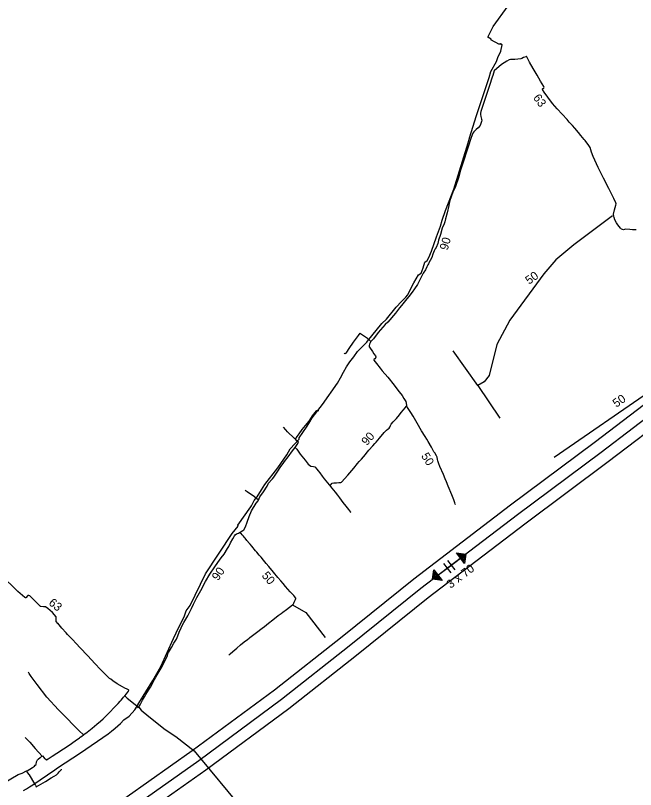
# Model space of a CAD drawing. Extents: x -444841 to -429545, y -1135312 to -1129851.
# Drawn here: x -442616 to -442033, y -1130962 to -1130233 of the extents above; entities that cross this region are included whole.
import ezdxf

# ---------------------------------------------------------------- set-up
doc = ezdxf.new("R2010")
doc.units = 0
for name, color, linetype in [('Vrstva 10', 7, 'Continuous'), ('Vrstva 13', 7, 'Continuous'), ('Vrstva 15', 7, 'Continuous'), ('Vrstva 27', 7, 'Continuous'), ('Vrstva 30', 7, 'Continuous'), ('Vrstva 35', 7, 'Continuous'), ('Vrstva 38', 7, 'Continuous'), ('Vrstva 58', 7, 'Continuous')]:
    doc.layers.add(name, color=color, linetype=linetype)

msp = doc.modelspace()

# ---------------------------------------------------------------- linework, layer by layer
at = {"layer": 'Vrstva 10'}
for p, q in [((-442209.39, -1130746.25), (-442206, -1130750.71)), ((-442213.18, -1130749.13), (-442209.79, -1130753.59)), ((-442209.79, -1130753.59), (-442206.4, -1130758.05)), ((-442206, -1130750.71), (-442202.61, -1130755.16))]:
    msp.add_line(p, q, dxfattribs=at)
for points in [[(-442545.2, -1131006.71), (-442443.5, -1130934.6), (-442365.65, -1130877.08), (-442301.93, -1130826.75), (-442234.54, -1130772.43), (-442143.45, -1130703.1), (-442064.73, -1130644.42), (-442003.9, -1130597.89), (-441963.63, -1130563.69)], [(-442218.48, -1130760.2), (-442207.89, -1130752.15), (-442197.31, -1130744.09)]]:
    msp.add_lwpolyline(points, dxfattribs=at)
for points in [[(-442201.13, -1130739.08), (-442192.3, -1130740.28), (-442193.49, -1130749.11)], [(-442199.54, -1130740), (-442193.09, -1130740.88), (-442193.96, -1130747.34)], [(-442197.97, -1130740.92), (-442193.87, -1130741.48), (-442194.43, -1130745.57)], [(-442196.38, -1130741.84), (-442194.66, -1130742.08), (-442194.89, -1130743.8)], [(-442222.29, -1130755.19), (-442214.66, -1130765.22), (-442223.49, -1130764.02)], [(-442221.83, -1130756.96), (-442216.24, -1130764.3), (-442222.7, -1130763.42)], [(-442221.36, -1130758.73), (-442217.82, -1130763.38), (-442221.92, -1130762.82)], [(-442220.89, -1130760.5), (-442219.4, -1130762.45), (-442221.13, -1130762.22)]]:
    msp.add_lwpolyline(points, close=True, dxfattribs=at)
at = {"layer": 'Vrstva 15'}
for points in [[(-441968.62, -1130553.5), (-442010.81, -1130589.32), (-442071.36, -1130635.64), (-442150.07, -1130694.32), (-442241.33, -1130763.77), (-442308.79, -1130818.15), (-442372.32, -1130868.34), (-442449.95, -1130925.69), (-442551.7, -1130997.84)], [(-442511.53, -1130996.32), (-442437.05, -1130943.51), (-442358.97, -1130885.82), (-442295.07, -1130835.35), (-442227.76, -1130781.09), (-442136.83, -1130711.89), (-442058.1, -1130653.2), (-441997, -1130606.45), (-441954.08, -1130570.1)]]:
    msp.add_lwpolyline(points, dxfattribs=at)
at = {"layer": 'Vrstva 27'}
for points in [[(-442079.9, -1130350.8), (-442080.72, -1130349.82), (-442083.95, -1130345.93), (-442086.15, -1130343.29), (-442089.78, -1130339.15), (-442091.92, -1130336.64), (-442094.89, -1130333.36), (-442096.98, -1130330.89), (-442101.71, -1130325.85), (-442106.2, -1130320.87), (-442110.6, -1130315.89), (-442115.09, -1130309.99), (-442118.55, -1130305.24), (-442120.18, -1130302.7), (-442120.27, -1130302.2), (-442120.02, -1130301.92), (-442118.78, -1130300.96), (-442118.58, -1130300.51), (-442118.71, -1130299.84), (-442121.95, -1130294.69), (-442125.17, -1130289.28), (-442128.95, -1130282.75), (-442132.23, -1130276.81), (-442134.8, -1130272.02), (-442135.03, -1130271.7), (-442135.38, -1130271.66), (-442135.88, -1130271.82), (-442137.84, -1130272.55), (-442139.54, -1130273.39), (-442140.42, -1130273.63), (-442146.25, -1130274.26), (-442150.32, -1130274.44), (-442151.4, -1130274.61), (-442153.72, -1130275.93), (-442158.67, -1130279.06), (-442165.58, -1130285.16)], [(-442165.58, -1130285.16), (-442166.88, -1130289.45), (-442167.31, -1130290.89), (-442170.05, -1130299.02), (-442171.29, -1130302.68), (-442174.92, -1130314.01), (-442178.05, -1130323.3), (-442178.43, -1130324.8), (-442178.55, -1130326.11), (-442178.07, -1130328.19), (-442177.45, -1130330.69), (-442177.24, -1130331.45), (-442177.48, -1130332.9), (-442178.76, -1130336.47), (-442180.61, -1130338.69), (-442182.41, -1130340.24), (-442184.85, -1130342.63), (-442185.71, -1130343.7), (-442186.41, -1130345.27), (-442187.82, -1130349.86), (-442189.76, -1130355.67), (-442191.72, -1130361.5), (-442193.78, -1130368.29), (-442197.14, -1130378.53)], [(-442031.87, -1130434.82), (-442035.46, -1130434.73), (-442037.75, -1130434.6), (-442042.06, -1130434.37), (-442043.97, -1130434.71), (-442045.64, -1130434.34), (-442046.75, -1130433.21), (-442049.07, -1130430.15), (-442050.26, -1130428.27), (-442051.88, -1130425.52), (-442052.67, -1130423.1), (-442052.98, -1130422.13), (-442053.1, -1130419.95), (-442052.32, -1130416.01), (-442050.91, -1130411.56), (-442050.78, -1130410.39), (-442050.99, -1130409.38), (-442052.9, -1130405.32), (-442057.74, -1130395.86), (-442062.69, -1130386.17), (-442067.8, -1130376.28), (-442072.48, -1130365.85), (-442073.91, -1130361.78), (-442075.3, -1130357.4), (-442076.35, -1130355.52), (-442079.9, -1130350.8)], [(-442197.14, -1130378.53), (-442199.28, -1130385.84), (-442201.84, -1130393.88), (-442204.37, -1130399.52), (-442207.36, -1130407.29), (-442208.2, -1130411.49), (-442208.3, -1130411.94), (-442209.73, -1130418.71), (-442211.51, -1130424.6), (-442212.15, -1130427.18), (-442212.65, -1130429.19), (-442214.45, -1130433.28), (-442216.13, -1130439.14), (-442217.86, -1130444.64), (-442218.73, -1130447.74), (-442220.3, -1130451.38), (-442221.02, -1130452.76), (-442222.1, -1130454.69), (-442223.41, -1130457.92), (-442224.26, -1130460.77), (-442225.8, -1130463.81), (-442227.12, -1130465.98), (-442227.4, -1130466.84), (-442227.85, -1130467.76), (-442228.85, -1130469.66), (-442230.13, -1130472.5), (-442232.42, -1130475.81), (-442235.19, -1130481.27), (-442237.14, -1130485.18), (-442237.76, -1130486.34), (-442240.52, -1130490.32), (-442242.89, -1130493.56), (-442245.96, -1130497.55), (-442247.87, -1130500)], [(-442247.87, -1130500), (-442250.29, -1130503.1), (-442252.71, -1130506.19), (-442254.54, -1130508.41), (-442258.54, -1130513.22), (-442265.66, -1130521.68), (-442268.09, -1130524.15), (-442274.83, -1130531.51), (-442279.22, -1130537.52), (-442281.59, -1130540.08)], [(-442291.86, -1130532.26), (-442293.5, -1130534.34), (-442298.37, -1130540.81), (-442302.22, -1130546.52), (-442304.59, -1130550.11), (-442305.44, -1130551.26), (-442306.03, -1130551.54), (-442306.68, -1130551.07)], [(-442281.59, -1130540.08), (-442284.89, -1130537.26), (-442291.32, -1130532.73), (-442291.86, -1130532.26)], [(-442281.59, -1130540.08), (-442281.92, -1130540.44), (-442282.37, -1130541.45), (-442282.77, -1130542.51), (-442283.29, -1130543.91), (-442283.21, -1130545.01), (-442282.95, -1130545.37), (-442280.01, -1130549.48), (-442278.78, -1130551.68), (-442277.22, -1130553.46), (-442276.85, -1130554.39), (-442276.61, -1130554.7), (-442276.87, -1130555.21), (-442277.89, -1130556.25), (-442278.86, -1130557.03), (-442278.95, -1130557.34), (-442278.8, -1130557.7), (-442276.4, -1130560.61), (-442272.79, -1130565.13), (-442270.84, -1130567.52), (-442265.7, -1130573.69), (-442259.83, -1130581.08), (-442257.28, -1130584.49), (-442254.94, -1130587.37), (-442252.29, -1130591.04), (-442250.71, -1130593.82), (-442248.82, -1130596.69), (-442248.31, -1130598.28), (-442248.06, -1130600.2), (-442248.38, -1130601.16)], [(-442320.61, -1130675.22), (-442319.77, -1130675.24), (-442318, -1130673.6), (-442316.5, -1130673.1), (-442314.08, -1130673.02), (-442311.65, -1130672.81), (-442309.84, -1130672.87), (-442309.29, -1130672.67), (-442303.37, -1130665.98), (-442297.79, -1130659.41), (-442294.18, -1130655.11), (-442292.52, -1130653.2), (-442290.57, -1130651.03), (-442286.77, -1130646.54), (-442285.98, -1130645.6), (-442283.39, -1130642.49), (-442279.7, -1130638.26), (-442277.87, -1130636.14), (-442276.71, -1130634.79), (-442273.61, -1130631.14), (-442269.14, -1130625.83), (-442266.9, -1130623.42), (-442265.42, -1130622.43), (-442264.32, -1130621.65), (-442263.64, -1130620.72), (-442263.12, -1130619.28), (-442262.65, -1130617.96), (-442260.54, -1130615.63), (-442257.6, -1130612.52), (-442254.77, -1130609.08), (-442253.03, -1130606.84), (-442251.01, -1130604.47), (-442249.25, -1130602.43), (-442248.38, -1130601.16)], [(-442201.94, -1130693.46), (-442202.21, -1130693.17), (-442202.65, -1130691.93), (-442203.45, -1130689.31), (-442205.53, -1130684.39), (-442208.76, -1130676.37), (-442210.5, -1130672.15), (-442211.65, -1130669.38), (-442213.38, -1130665.19), (-442216.65, -1130657.73), (-442217.63, -1130655.34), (-442218.73, -1130652.39), (-442218.94, -1130651.34), (-442219.32, -1130649.02), (-442219.85, -1130647.62), (-442221.48, -1130644.78), (-442222.29, -1130643.91), (-442222.7, -1130643.48), (-442224.43, -1130639.7), (-442227.65, -1130634.29), (-442228.93, -1130632.16), (-442230.36, -1130629.68), (-442233.87, -1130624.07), (-442238.08, -1130616.86), (-442241.92, -1130610.41), (-442244.07, -1130606.83), (-442247.26, -1130602.3), (-442248.38, -1130601.16)], [(-442352.69, -1130632.19), (-442350.93, -1130629.68), (-442349.03, -1130627.11), (-442346.18, -1130623.08), (-442343.03, -1130619.16), (-442339.76, -1130615.19), (-442336.51, -1130610), (-442332.91, -1130605.29), (-442332.52, -1130605.05), (-442331.52, -1130604.93), (-442330.64, -1130604.95)], [(-442353.75, -1130631.17), (-442360.16, -1130624.99), (-442361.82, -1130623.33), (-442363.89, -1130620.79)], [(-442352.69, -1130632.19), (-442353.49, -1130631.42), (-442353.75, -1130631.17)], [(-442352.75, -1130640.01), (-442352.32, -1130638.86), (-442351.13, -1130637.01), (-442349.75, -1130635.02), (-442351.18, -1130633.69), (-442352.69, -1130632.19)], [(-442387.32, -1130689.35), (-442386.01, -1130686.48), (-442382.71, -1130681.51), (-442379.25, -1130676.28), (-442378.01, -1130673.54), (-442374.87, -1130670.06), (-442374.38, -1130669.55), (-442373.1, -1130667.99), (-442369.84, -1130663.28), (-442366.23, -1130657.88), (-442364.28, -1130654.99), (-442362.81, -1130653.05), (-442359.56, -1130648.67), (-442355.25, -1130642.91), (-442352.75, -1130640.01)], [(-442352.75, -1130640.01), (-442351.33, -1130641.47), (-442348.04, -1130646.25), (-442343.34, -1130651.95), (-442340.59, -1130655.7), (-442338.07, -1130657.38), (-442335.73, -1130657.72), (-442334.28, -1130658.1), (-442334.08, -1130658.35), (-442332.49, -1130660.29), (-442331.1, -1130661.99), (-442329.7, -1130663.86), (-442327.39, -1130666.83), (-442325.44, -1130669.32), (-442322.51, -1130673.1), (-442320.92, -1130675), (-442320.61, -1130675.22)], [(-442320.61, -1130675.22), (-442318.48, -1130678.11), (-442315.37, -1130681.85), (-442313, -1130684.89), (-442311.23, -1130687.28), (-442307.97, -1130691.59), (-442305.32, -1130695.09), (-442302.73, -1130698.36), (-442300.88, -1130700.73), (-442300.45, -1130701.22)], [(-442387.32, -1130689.35), (-442391.21, -1130686.5), (-442398.2, -1130681.76), (-442399.9, -1130680.39)], [(-442404.65, -1130719.63), (-442403.79, -1130719.17), (-442402.14, -1130718.14), (-442401.31, -1130717.43), (-442399.57, -1130714.59), (-442398.21, -1130710.1), (-442396.1, -1130704.97), (-442393.96, -1130699.64), (-442389.62, -1130692.47), (-442387.62, -1130690), (-442387.32, -1130689.35)], [(-442500, -1130884.03), (-442498.94, -1130882.24), (-442496.5, -1130877.86), (-442494.71, -1130874.85), (-442493.35, -1130872.5), (-442490.9, -1130868.51), (-442489.18, -1130865.74), (-442486.72, -1130861.6), (-442485.2, -1130858.46), (-442484.18, -1130856.15), (-442481.71, -1130852.34), (-442478.99, -1130847.84), (-442476, -1130841.74), (-442473.1, -1130835.79), (-442472.63, -1130834.21), (-442472.03, -1130833.09), (-442469.21, -1130828.13), (-442467.07, -1130824.33), (-442464.75, -1130820.34), (-442463.33, -1130817.18), (-442462.07, -1130813.91), (-442460.31, -1130809.81), (-442459.82, -1130808.79), (-442457.54, -1130804.64), (-442453.9, -1130798.59), (-442452.25, -1130795.41), (-442450.47, -1130791.56), (-442448.47, -1130787.49), (-442445.3, -1130781.06), (-442441.74, -1130774.54), (-442437.18, -1130766.17), (-442433.17, -1130759.16), (-442428.46, -1130752.2), (-442425.55, -1130748.19), (-442422.5, -1130743.9), (-442419.83, -1130740.21), (-442416.57, -1130734.92), (-442415.44, -1130733.09), (-442413.68, -1130729.78), (-442411.64, -1130725.93), (-442410.44, -1130723.75), (-442409.89, -1130723.02), (-442409.41, -1130722.21), (-442408.03, -1130721.23), (-442406.28, -1130720.57), (-442404.65, -1130719.63)], [(-442404.31, -1130825.74), (-442400.75, -1130822.87), (-442397.82, -1130820.7), (-442396.27, -1130819.36), (-442395.56, -1130818.81), (-442393.06, -1130816.86), (-442389.17, -1130814), (-442383.92, -1130810.07), (-442381.75, -1130808.44), (-442378.08, -1130805.45), (-442373.92, -1130802.27), (-442368.88, -1130798.25), (-442366.08, -1130796.12), (-442364.62, -1130795.05), (-442361.02, -1130792.4), (-442355.27, -1130788), (-442354.61, -1130787.25), (-442354.21, -1130786.56), (-442353.84, -1130785.73), (-442352.52, -1130783.05), (-442352.21, -1130782.23), (-442352.21, -1130782.2), (-442352.24, -1130781.82), (-442352.58, -1130781.38), (-442353.17, -1130780.71), (-442354.3, -1130779.43), (-442357.73, -1130775.74), (-442361.93, -1130770.89), (-442364.33, -1130767.96), (-442366.37, -1130765.64), (-442369.22, -1130762.35), (-442373.4, -1130757.23), (-442377.55, -1130752.09), (-442380.25, -1130749.07), (-442382.55, -1130746.15), (-442385.01, -1130743.32), (-442386.82, -1130741.29), (-442389.11, -1130738.47), (-442389.68, -1130737.77), (-442390.26, -1130737.08), (-442393.73, -1130732.9), (-442395.13, -1130731.1), (-442395.89, -1130730.17), (-442398.27, -1130727.48), (-442400.03, -1130725.42), (-442401.01, -1130724.28), (-442401.65, -1130723.48), (-442401.97, -1130723.13), (-442402.91, -1130722.08), (-442404.6, -1130719.69), (-442404.65, -1130719.63)], [(-442602.71, -1130779.69), (-442603.48, -1130779.37), (-442604.45, -1130779.32), (-442606.52, -1130781.39), (-442606.86, -1130781.47), (-442607.46, -1130781.28), (-442613.91, -1130775.41), (-442620.53, -1130768.88), (-442626.35, -1130763.61), (-442629.05, -1130762.08), (-442630.9, -1130761.59), (-442631.13, -1130761.67)], [(-442592.28, -1130789.81), (-442592.7, -1130789.71), (-442592.71, -1130789.72), (-442602.71, -1130779.69)], [(-442577.85, -1130803.83), (-442578.01, -1130799.34), (-442581.21, -1130795.23), (-442585.74, -1130791.57), (-442587.9, -1130790.01), (-442589.92, -1130789.96), (-442592.28, -1130789.81)], [(-442567.09, -1130815.96), (-442568.42, -1130814.49), (-442572.38, -1130809.95), (-442576.42, -1130805.44), (-442576.32, -1130805.54), (-442577.85, -1130803.83)], [(-442513.19, -1130873.94), (-442511.81, -1130871.97), (-442509.75, -1130869.31), (-442509.34, -1130868.5), (-442509.73, -1130868.07), (-442511.08, -1130867.46), (-442513.19, -1130866.56), (-442515.32, -1130865.48), (-442520.57, -1130862.51), (-442524.45, -1130859.74), (-442526.55, -1130858.15), (-442527.59, -1130857.37), (-442530.6, -1130854.55), (-442536.15, -1130848.89), (-442541.4, -1130843.45), (-442548.16, -1130836.24), (-442555.55, -1130828.17), (-442558.88, -1130824.72), (-442562.93, -1130820.52), (-442567.09, -1130815.96)], [(-442415.28, -1130835.64), (-442413.95, -1130834.39), (-442411.65, -1130832.01), (-442407.94, -1130828.86), (-442404.31, -1130825.74)], [(-442551.99, -1130910.44), (-442556.22, -1130906.67), (-442561.34, -1130901.65), (-442568.01, -1130894.68), (-442575.79, -1130886.87), (-442586.71, -1130875.16), (-442595.64, -1130862.98), (-442601.36, -1130855.51), (-442603.29, -1130852.73), (-442603.65, -1130852.12), (-442603.92, -1130851.48)], [(-442551.99, -1130910.44), (-442551.72, -1130910.23), (-442548.56, -1130907.88), (-442543.89, -1130904.2), (-442539.48, -1130900.44), (-442536.29, -1130897.59), (-442533.59, -1130895.42), (-442531.1, -1130893.04), (-442527.03, -1130889), (-442523.49, -1130885.17), (-442519.55, -1130880.9), (-442517.68, -1130878.91), (-442516.78, -1130877.96), (-442515.51, -1130876.3), (-442514.6, -1130875.11), (-442513.19, -1130873.94)], [(-442513.19, -1130873.94), (-442511.02, -1130875.96), (-442509.81, -1130876.82), (-442503.12, -1130882.28), (-442502.01, -1130883.66), (-442500.69, -1130885.02), (-442500.2, -1130884.37), (-442500, -1130884.03)], [(-442607.15, -1130912.96), (-442605.99, -1130914.13), (-442602.79, -1130917.45), (-442597.68, -1130923.38), (-442591.13, -1130930.6)], [(-442591.13, -1130930.6), (-442590.74, -1130930.25), (-442589.08, -1130932.18), (-442587.04, -1130934.19), (-442585.49, -1130933.21), (-442581.56, -1130930.63), (-442577.28, -1130927.7), (-442571.11, -1130923.6), (-442565.71, -1130920.22), (-442560.1, -1130916.22), (-442555.98, -1130913.22), (-442555.34, -1130912.68), (-442553.86, -1130911.86), (-442551.99, -1130910.44)], [(-442605.65, -1130944.6), (-442605.32, -1130944.44), (-442602.56, -1130942.85), (-442600.05, -1130941.28), (-442598.34, -1130940.09), (-442597.51, -1130939.2), (-442596.67, -1130938.47), (-442596.32, -1130935.94), (-442595.34, -1130934.22), (-442594.72, -1130933.45), (-442593.07, -1130932.02), (-442592.19, -1130931.63), (-442591.32, -1130930.77), (-442591.13, -1130930.6)], [(-442644.93, -1130964.24), (-442639.49, -1130962.01), (-442635.36, -1130959.97), (-442630.59, -1130957.63), (-442626.89, -1130955.51), (-442623.7, -1130953.84), (-442620.43, -1130951.84), (-442613.54, -1130948.05), (-442609.85, -1130946.56), (-442605.65, -1130944.6)], [(-442605.65, -1130944.6), (-442605.08, -1130945.88), (-442603.3, -1130948.34), (-442598.28, -1130956.7), (-442597.66, -1130957.79), (-442597.39, -1130958.09), (-442597.15, -1130958.56), (-442596.62, -1130959.52)], [(-442596.62, -1130959.52), (-442594.54, -1130958.31), (-442592.25, -1130956.98), (-442587.94, -1130954.38), (-442582.46, -1130951.02), (-442579.71, -1130949.63), (-442577.61, -1130948.1), (-442576.05, -1130946.54), (-442574.94, -1130945.32), (-442573.08, -1130943.41), (-442572.79, -1130943.11), (-442572.81, -1130942.94), (-442572.84, -1130942.78)]]:
    msp.add_lwpolyline(points, dxfattribs=at)
at = {"layer": 'Vrstva 35'}
for p, q in [((-442109.22, -1130649.14), (-441962.74, -1130547.8)), ((-442180.87, -1130581.64), (-442160.31, -1130612.19))]:
    msp.add_line(p, q, dxfattribs=at)
for points in [[(-442054.2, -1130421.58), (-442090.58, -1130449.08), (-442107.45, -1130463.21), (-442118.7, -1130476.23), (-442150.67, -1130520.05), (-442163.17, -1130542.96), (-442170.21, -1130572.16), (-442174.95, -1130578.08), (-442180.87, -1130581.64), (-442204.28, -1130548.79)], [(-442355.27, -1130788), (-442342.74, -1130795.22), (-442324.77, -1130818.79)], [(-442500.2, -1130884.37), (-442497.82, -1130887.18), (-442490.69, -1130893.39), (-442475.17, -1130905.39), (-442465.35, -1130912.21), (-442448.01, -1130925.49), (-442401.17, -1130982.2), (-442388.78, -1130994.41), (-442378.11, -1131004.41), (-442338.15, -1131041.79), (-442319.45, -1131059.9), (-442262, -1131115.01)]]:
    msp.add_lwpolyline(points, dxfattribs=at)
at = {"layer": 'Vrstva 58'}
for points in [[(-442168.69, -1130285.83), (-442163.33, -1130276.21), (-442162, -1130272.56), (-442159.36, -1130266.71), (-442157.94, -1130260.51), (-442159.56, -1130259.6), (-442160.01, -1130259.2), (-442160.51, -1130260.25), (-442168.79, -1130255.9), (-442168.24, -1130255.5), (-442168.29, -1130255.21), (-442171.63, -1130253.27), (-442166.44, -1130243.47), (-442138.31, -1130204.19), (-442119.03, -1130174.17), (-442103.65, -1130142.05)], [(-442509.18, -1130893.03), (-442503.86, -1130887.08), (-442503.05, -1130886.01), (-442500.19, -1130880.75), (-442486.96, -1130859.4), (-442479.34, -1130846.03), (-442467.57, -1130819.67), (-442464.96, -1130814.41), (-442463.13, -1130810.27), (-442457.32, -1130799.28), (-442455.43, -1130793.9), (-442451.66, -1130788.8), (-442437.16, -1130758.81), (-442412.14, -1130720.81), (-442406.68, -1130714.08), (-442406.78, -1130713), (-442394.69, -1130695.86), (-442394.05, -1130694.78), (-442391.45, -1130689.81), (-442388.76, -1130686.34), (-442384.63, -1130679.66), (-442381.3, -1130674.88), (-442369.35, -1130659.06), (-442360.63, -1130646.64), (-442357.61, -1130641.17), (-442349.25, -1130632.1), (-442349.22, -1130630.83), (-442342.3, -1130620.88), (-442339.87, -1130617.14), (-442336.8, -1130612.09), (-442327.15, -1130599.28), (-442312.93, -1130579.28), (-442310.16, -1130574.11), (-442307.48, -1130569.01), (-442304.49, -1130563.8), (-442301.33, -1130559.11), (-442297.77, -1130554.45), (-442294.1, -1130549.55), (-442285.45, -1130540.58), (-442284.89, -1130539.87), (-442271.3, -1130523), (-442266.92, -1130519.08), (-442257.88, -1130507.58), (-442252.78, -1130502.25), (-442248.6, -1130498.27), (-442247.06, -1130496.33), (-442241.03, -1130484.83), (-442236.73, -1130477.37), (-442234.42, -1130475.63), (-442232.55, -1130470.65), (-442230.72, -1130465.43), (-442228.78, -1130463.7), (-442227.15, -1130460.84), (-442224.46, -1130455.07), (-442219.98, -1130441.43), (-442216.03, -1130431.4), (-442214.43, -1130425.83), (-442211.44, -1130416.63), (-442203.63, -1130396.6), (-442190.03, -1130352.82), (-442188.43, -1130347.2), (-442182.55, -1130328.05), (-442180.53, -1130322.58), (-442170.21, -1130291.28), (-442168.69, -1130285.83)], [(-442608.75, -1130963.13), (-442605.79, -1130961.53), (-442602.87, -1130959.46), (-442599.81, -1130957.52), (-442579, -1130943.47), (-442576.59, -1130941.76), (-442555.02, -1130927.44), (-442528.93, -1130909.45), (-442525.77, -1130907.12), (-442522.2, -1130904.12), (-442517.4, -1130899.83), (-442514.02, -1130896.31), (-442509.18, -1130893.03)]]:
    msp.add_lwpolyline(points, dxfattribs=at)

# ---------------------------------------------------------------- texts
at = {"layer": 'Vrstva 13'}
msp.add_text('3 x 70', height=8, rotation=37.27331, dxfattribs=at).set_placement((-442206.57, -1130773.09))
at = {"layer": 'Vrstva 30'}
for s, rotation, p in [('63', 306.07038, (-442129.31, -1130310.5)), ('90', 74.32348, (-442209.41, -1130454.63)), ('90', 49.00577, (-442285.35, -1130638.63)), ('50', 302.03292, (-442234.66, -1130647.78)), ('90', 55.91284, (-442425.43, -1130765.93)), ('50', 310.31289, (-442384.85, -1130760.8)), ('63', 321.05597, (-442585.64, -1130787.34))]:
    msp.add_text(s, height=8, rotation=rotation, dxfattribs=at).set_placement(p)
at = {"layer": 'Vrstva 38'}
for rotation, p in [(35.83178, (-442132.67, -1130486.73)), (34.67656, (-442050.62, -1130602.52))]:
    msp.add_text('50', height=8, rotation=rotation, dxfattribs=at).set_placement(p)

doc.saveas('drawing.dxf')
